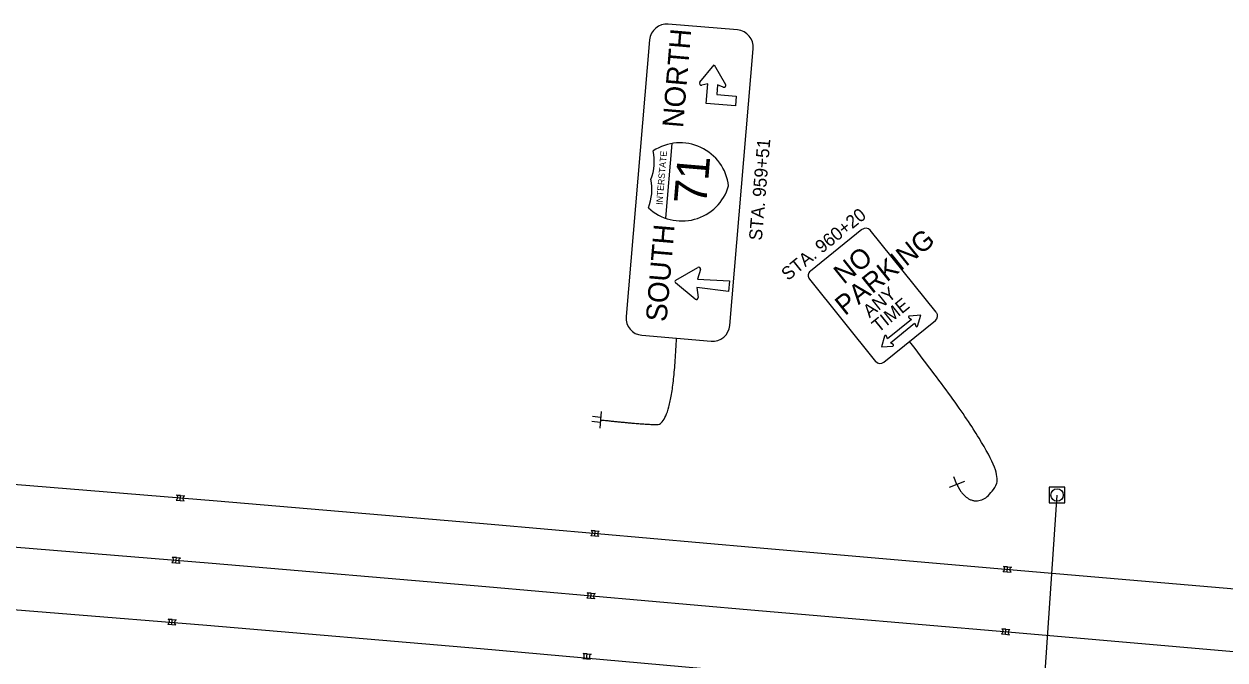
# Model space of a CAD drawing. Extents: x 1847379 to 1850904, y 217032 to 220169.
# Drawn here: x 1849979.4 to 1850210.2, y 218780.5 to 218902.7 of the extents above; entities that cross this region are included whole.
import ezdxf

# ---------------------------------------------------------------- set-up
doc = ezdxf.new("R2010")
doc.units = 0
for name, color, linetype in [('PM_P_Cells', 7, 'Continuous'), ('PM_P_Edge_Line', 7, 'Continuous'), ('PM_P_Lane_Line', 7, 'Continuous'), ('SG_X_Poles', 7, 'Continuous'), ('SN_X_Public', 7, 'Continuous'), ('SN_X_Text', 7, 'Continuous')]:
    doc.layers.add(name, color=color, linetype=linetype)

msp = doc.modelspace()

# ---------------------------------------------------------------- linework, layer by layer
at = {"layer": 'PM_P_Cells'}
for p, q in [((1850009.49, 218812.16), (1850008.72, 218812.22)), ((1850008.72, 218812.22), (1850009.49, 218812.16)), ((1850009.4, 218811.18), (1850009.49, 218812.16)), ((1850009.49, 218812.16), (1850010.25, 218812.09)), ((1850008.63, 218811.25), (1850009.4, 218811.18)), ((1850008.63, 218811.25), (1850009.4, 218811.18)), ((1850009.4, 218811.18), (1850010.17, 218811.11)), ((1850089.21, 218805.34), (1850088.44, 218805.41)), ((1850088.44, 218805.41), (1850089.21, 218805.34)), ((1850089.12, 218804.37), (1850089.21, 218805.34)), ((1850089.21, 218805.34), (1850089.98, 218805.27)), ((1850088.35, 218804.44), (1850089.12, 218804.37)), ((1850088.35, 218804.44), (1850089.12, 218804.37)), ((1850089.12, 218804.37), (1850089.89, 218804.3)), ((1850007.83, 218799.29), (1850008.6, 218799.22)), ((1850007.83, 218799.29), (1850008.6, 218799.22)), ((1850008.69, 218800.2), (1850007.92, 218800.27)), ((1850007.92, 218800.27), (1850008.69, 218800.2)), ((1850008.6, 218799.22), (1850008.69, 218800.2)), ((1850008.6, 218799.22), (1850009.37, 218799.15)), ((1850008.69, 218800.2), (1850009.45, 218800.13)), ((1850168.43, 218798.45), (1850167.66, 218798.52)), ((1850167.66, 218798.52), (1850168.43, 218798.45)), ((1850168.34, 218797.48), (1850168.43, 218798.45)), ((1850168.43, 218798.45), (1850169.19, 218798.38)), ((1850167.57, 218797.55), (1850168.34, 218797.48)), ((1850167.57, 218797.55), (1850168.34, 218797.48)), ((1850168.34, 218797.48), (1850169.11, 218797.41)), ((1850087.55, 218792.46), (1850088.32, 218792.39)), ((1850087.55, 218792.46), (1850088.32, 218792.39)), ((1850088.41, 218793.37), (1850087.64, 218793.44)), ((1850087.64, 218793.44), (1850088.41, 218793.37)), ((1850088.32, 218792.39), (1850088.41, 218793.37)), ((1850088.32, 218792.39), (1850089.09, 218792.32)), ((1850088.41, 218793.37), (1850089.18, 218793.3)), ((1850007.04, 218787.42), (1850007.81, 218787.35)), ((1850007.04, 218787.42), (1850007.81, 218787.35)), ((1850007.89, 218788.32), (1850007.13, 218788.39)), ((1850007.13, 218788.39), (1850007.89, 218788.32)), ((1850007.81, 218787.35), (1850007.89, 218788.32)), ((1850007.81, 218787.35), (1850008.57, 218787.28)), ((1850007.89, 218788.32), (1850008.66, 218788.25)), ((1850167.27, 218785.53), (1850168.04, 218785.46)), ((1850167.27, 218785.53), (1850168.04, 218785.46)), ((1850168.12, 218786.43), (1850167.36, 218786.5)), ((1850167.36, 218786.5), (1850168.12, 218786.43)), ((1850168.04, 218785.46), (1850168.12, 218786.43)), ((1850168.04, 218785.46), (1850168.8, 218785.39)), ((1850168.12, 218786.43), (1850168.89, 218786.36)), ((1850086.78, 218780.81), (1850087.54, 218780.74)), ((1850086.78, 218780.81), (1850087.54, 218780.74)), ((1850087.63, 218781.72), (1850086.86, 218781.79)), ((1850086.86, 218781.79), (1850087.63, 218781.72)), ((1850087.54, 218780.74), (1850087.63, 218781.72)), ((1850087.54, 218780.74), (1850088.31, 218780.67)), ((1850087.63, 218781.72), (1850088.4, 218781.65))]:
    msp.add_line(p, q, dxfattribs=at)
for centre, start, end in [((1850008.37, 218811.77), 296.8063, 52.8586), ((1850008.37, 218811.77), 296.8063, 52.8586), ((1850010.51, 218811.57), 116.8063, 232.8586), ((1850088.09, 218804.95), 296.8063, 52.8586), ((1850088.09, 218804.95), 296.8063, 52.8586), ((1850090.24, 218804.76), 116.8063, 232.8586), ((1850007.57, 218799.81), 296.8063, 52.8586), ((1850007.57, 218799.81), 296.8063, 52.8586), ((1850009.71, 218799.61), 116.8063, 232.8586), ((1850167.31, 218798.06), 296.8063, 52.8586), ((1850167.31, 218798.06), 296.8063, 52.8586), ((1850169.45, 218797.87), 116.8063, 232.8586), ((1850087.29, 218792.98), 296.8063, 52.8586), ((1850087.29, 218792.98), 296.8063, 52.8586), ((1850089.44, 218792.78), 116.8063, 232.8586), ((1850006.78, 218787.93), 296.8063, 52.8586), ((1850006.78, 218787.93), 296.8063, 52.8586), ((1850008.92, 218787.74), 116.8063, 232.8586), ((1850167.01, 218786.04), 296.8063, 52.8586), ((1850167.01, 218786.04), 296.8063, 52.8586), ((1850169.15, 218785.85), 116.8063, 232.8586), ((1850086.52, 218781.33), 296.8063, 52.8586), ((1850086.52, 218781.33), 296.8063, 52.8586), ((1850088.66, 218781.13), 116.8063, 232.8586)]:
    msp.add_arc(centre, 0.576, start, end, dxfattribs=at)
at = {"layer": 'PM_P_Edge_Line'}
msp.add_lwpolyline([(1849889.22, 218821.46), (1849908.57, 218819.63), (1849959.34, 218815.75), (1850016.54, 218811.11), (1850069.2, 218806.62), (1850120.11, 218802.11), (1850169.53, 218797.86), (1850218.84, 218793.6), (1850268.16, 218788.98), (1850318.46, 218784.1), (1850367.53, 218779.29), (1850417.75, 218774.53), (1850467.84, 218769.49), (1850519.01, 218764.5), (1850567.74, 218759.83), (1850617.52, 218754.84), (1850666.94, 218749.6)], dxfattribs=at)
at = {"layer": 'PM_P_Lane_Line'}
for points in [[(1849608.99, 218828.81), (1849660.31, 218825.18), (1849710.18, 218821.58), (1849761.09, 218817.87), (1849808.06, 218814.41), (1849858.45, 218811.1), (1849907.69, 218807.67), (1849958.4, 218803.79), (1850015.55, 218799.15), (1850068.16, 218794.66), (1850119.07, 218790.16), (1850168.5, 218785.91), (1850217.76, 218781.65), (1850267.02, 218777.03), (1850317.3, 218772.15), (1850366.38, 218767.35), (1850416.59, 218762.59), (1850466.65, 218757.55), (1850517.86, 218752.55), (1850566.57, 218747.88), (1850616.29, 218742.91), (1850664.9, 218737.75)], [(1849608.14, 218816.84), (1849659.46, 218813.21), (1849709.31, 218809.62), (1849760.21, 218805.9), (1849807.22, 218802.44), (1849857.63, 218799.12), (1849906.82, 218795.7), (1849957.46, 218791.82), (1850014.55, 218787.19), (1850067.13, 218782.71), (1850118.03, 218778.2), (1850167.47, 218773.95), (1850186.14, 218772.34)]]:
    msp.add_lwpolyline(points, dxfattribs=at)
at = {"layer": 'SG_X_Poles'}
msp.add_lwpolyline([(1850176.46, 218810.72), (1850179.46, 218810.72), (1850179.46, 218813.72), (1850176.46, 218813.72)], close=True, dxfattribs=at)
msp.add_circle((1850177.96, 218812.22), 1.2, dxfattribs=at)
at = {"layer": 'SN_X_Public'}
for p, q in [((1850109.31, 218891.53), (1850112.08, 218894.84)), ((1850112.08, 218894.84), (1850114.26, 218891.11)), ((1850110.83, 218891.2), (1850109.67, 218890.94)), ((1850110.52, 218887.45), (1850110.83, 218891.2)), ((1850112.7, 218891.04), (1850112.54, 218889.16)), ((1850113.81, 218890.58), (1850112.7, 218891.04)), ((1850112.5, 218890.2), (1850112.5, 218890.2)), ((1850112.54, 218889.16), (1850116.28, 218888.84)), ((1850116.28, 218888.84), (1850116.12, 218886.97)), ((1850116.12, 218886.97), (1850110.52, 218887.45)), ((1850102.77, 218865.39), (1850103.99, 218879.76)), ((1850107.35, 218872.24), (1850107.35, 218872.24)), ((1850104.66, 218853.51), (1850108.94, 218855.94)), ((1850109.43, 218855.54), (1850108.82, 218853.66)), ((1850108.82, 218853.66), (1850114.97, 218853.4)), ((1850108.42, 218849.84), (1850104.62, 218852.96)), ((1850114.79, 218851.33), (1850108.69, 218852.11)), ((1850108.69, 218852.11), (1850108.97, 218850.15)), ((1850109.33, 218852.84), (1850109.33, 218852.84)), ((1850114.97, 218853.4), (1850114.79, 218851.33)), ((1850151.75, 218846.75), (1850149.59, 218846.61)), ((1850151.15, 218844.67), (1850151.75, 218846.75)), ((1850149.99, 218845.94), (1850145.36, 218842.21)), ((1850149.5, 218846.28), (1850150, 218845.95)), ((1850150, 218845.95), (1850149.99, 218845.94)), ((1850150.59, 218845.22), (1850150.8, 218844.66)), ((1850144.8, 218842.75), (1850144.2, 218840.67)), ((1850145.36, 218842.21), (1850145.15, 218842.77)), ((1850145.36, 218842.21), (1850145.37, 218842.21)), ((1850148.17, 218843.49), (1850148.17, 218843.49)), ((1850144.2, 218840.67), (1850146.36, 218840.82)), ((1850146.45, 218841.15), (1850145.95, 218841.48)), ((1850090.33, 218828.25), (1850090.05, 218825.06)), ((1850090.15, 218826.18), (1850088.56, 218826.32)), ((1850090.23, 218827.14), (1850088.64, 218827.28)), ((1850090.19, 218826.66), (1850090.19, 218826.66)), ((1850160.19, 218814.85), (1850157.22, 218813.65)), ((1850158.71, 218814.25), (1850158.11, 218815.73)), ((1850170.32, 218698.83), (1850177.96, 218812.22))]:
    msp.add_line(p, q, dxfattribs=at)
for points in [[(1850116.53, 218901.57), (1850103.24, 218902.69)], [(1850099.64, 218899.66), (1850095.13, 218846.51)], [(1850115.06, 218844.82), (1850119.57, 218897.96)], [(1850140.46, 218863.25), (1850130.54, 218855.25)], [(1850154.75, 218847.32), (1850142.04, 218863.08)], [(1850130.37, 218853.67), (1850143.07, 218837.9)], [(1850144.65, 218837.73), (1850154.58, 218845.73)], [(1850145.95, 218841.48), (1850150.58, 218845.21)], [(1850098.17, 218842.91), (1850111.45, 218841.78)]]:
    msp.add_lwpolyline(points, dxfattribs=at)
for centre, radius, start, end in [((1850102.96, 218899.37), 3.33, 85.1482, 175.1482), ((1850116.25, 218898.25), 3.33, 355.1482, 85.1482), ((1850109.59, 218891.29), 0.365, 140.0689, 282.786), ((1850113.95, 218890.92), 0.365, 247.5104, 30.2274), ((1850105.51, 218870.51), 9.38, 6.6851, 123.4792), ((1850091.17, 218876.36), 9.38, 338.1572, 12.1391), ((1850090.71, 218870.9), 9.38, 338.1572, 12.1391), ((1850105.83, 218874.25), 9.38, 226.8171, 343.6112), ((1850141.17, 218862.38), 1.12, 38.8676, 128.8676), ((1850109.1, 218855.65), 0.338, 342.1719, 119.6453), ((1850104.84, 218853.22), 0.338, 121.0545, 229.2418), ((1850131.24, 218854.38), 1.12, 128.8676, 218.8676), ((1850108.63, 218850.1), 0.338, 230.651, 8.1244), ((1850149.6, 218846.43), 0.182, 93.7884, 236.5054), ((1850153.88, 218846.61), 1.12, 308.8676, 38.8676), ((1850098.45, 218846.23), 3.33, 175.1482, 265.1482), ((1850111.74, 218845.1), 3.33, 265.1482, 355.1482), ((1850150.97, 218844.72), 0.182, 201.2298, 343.9469), ((1850144.98, 218842.7), 0.182, 21.2298, 163.9469), ((1850146.35, 218841), 0.182, 273.7884, 56.5054), ((1850143.95, 218838.61), 1.12, 218.8676, 308.8676)]:
    msp.add_arc(centre, radius, start, end, dxfattribs=at)
at = {"layer": 'SN_X_Text'}
for points in [[(1850090.19, 218826.66), (1850097.85, 218825.82), (1850104.14, 218825.7), (1850104.81, 218842.35)], [(1850158.71, 218814.25), (1850160.12, 218811.24), (1850164.56, 218810.96), (1850168.12, 218817.91), (1850149.62, 218841.73)]]:
    msp.add_open_spline(points, degree=2, dxfattribs=at)

# ---------------------------------------------------------------- texts
at = {"layer": 'SN_X_Public'}
for s, height, rotation, p in [('NORTH', 4, 85.1482, (1850106.06, 218882.67)), ('INTERSTATE', 1.25, 85.1482, (1850102.12, 218867.93)), ('71', 6.25, 85.1482, (1850110.51, 218867.9)), ('SOUTH', 4, 85.1482, (1850102.89, 218845.39)), ('PARKING', 3.75, 38.8676, (1850137.2, 218846.57)), ('NO', 3.75, 38.8676, (1850136.95, 218852.59)), ('ANY', 2.5, 38.8676, (1850141.91, 218846.16)), ('TIME', 2.5, 38.8676, (1850143.62, 218843.32))]:
    msp.add_text(s, height=height, rotation=rotation, dxfattribs=at).set_placement(p)
at = {"layer": 'SN_X_Text'}
for s, rotation, p in [('STA. 959+51', 85.1482, (1850121.21, 218861.05)), ('STA. 960+20', 38.8676, (1850126.22, 218853.29))]:
    msp.add_text(s, height=2.5, rotation=rotation, dxfattribs=at).set_placement(p)

doc.saveas('drawing.dxf')
